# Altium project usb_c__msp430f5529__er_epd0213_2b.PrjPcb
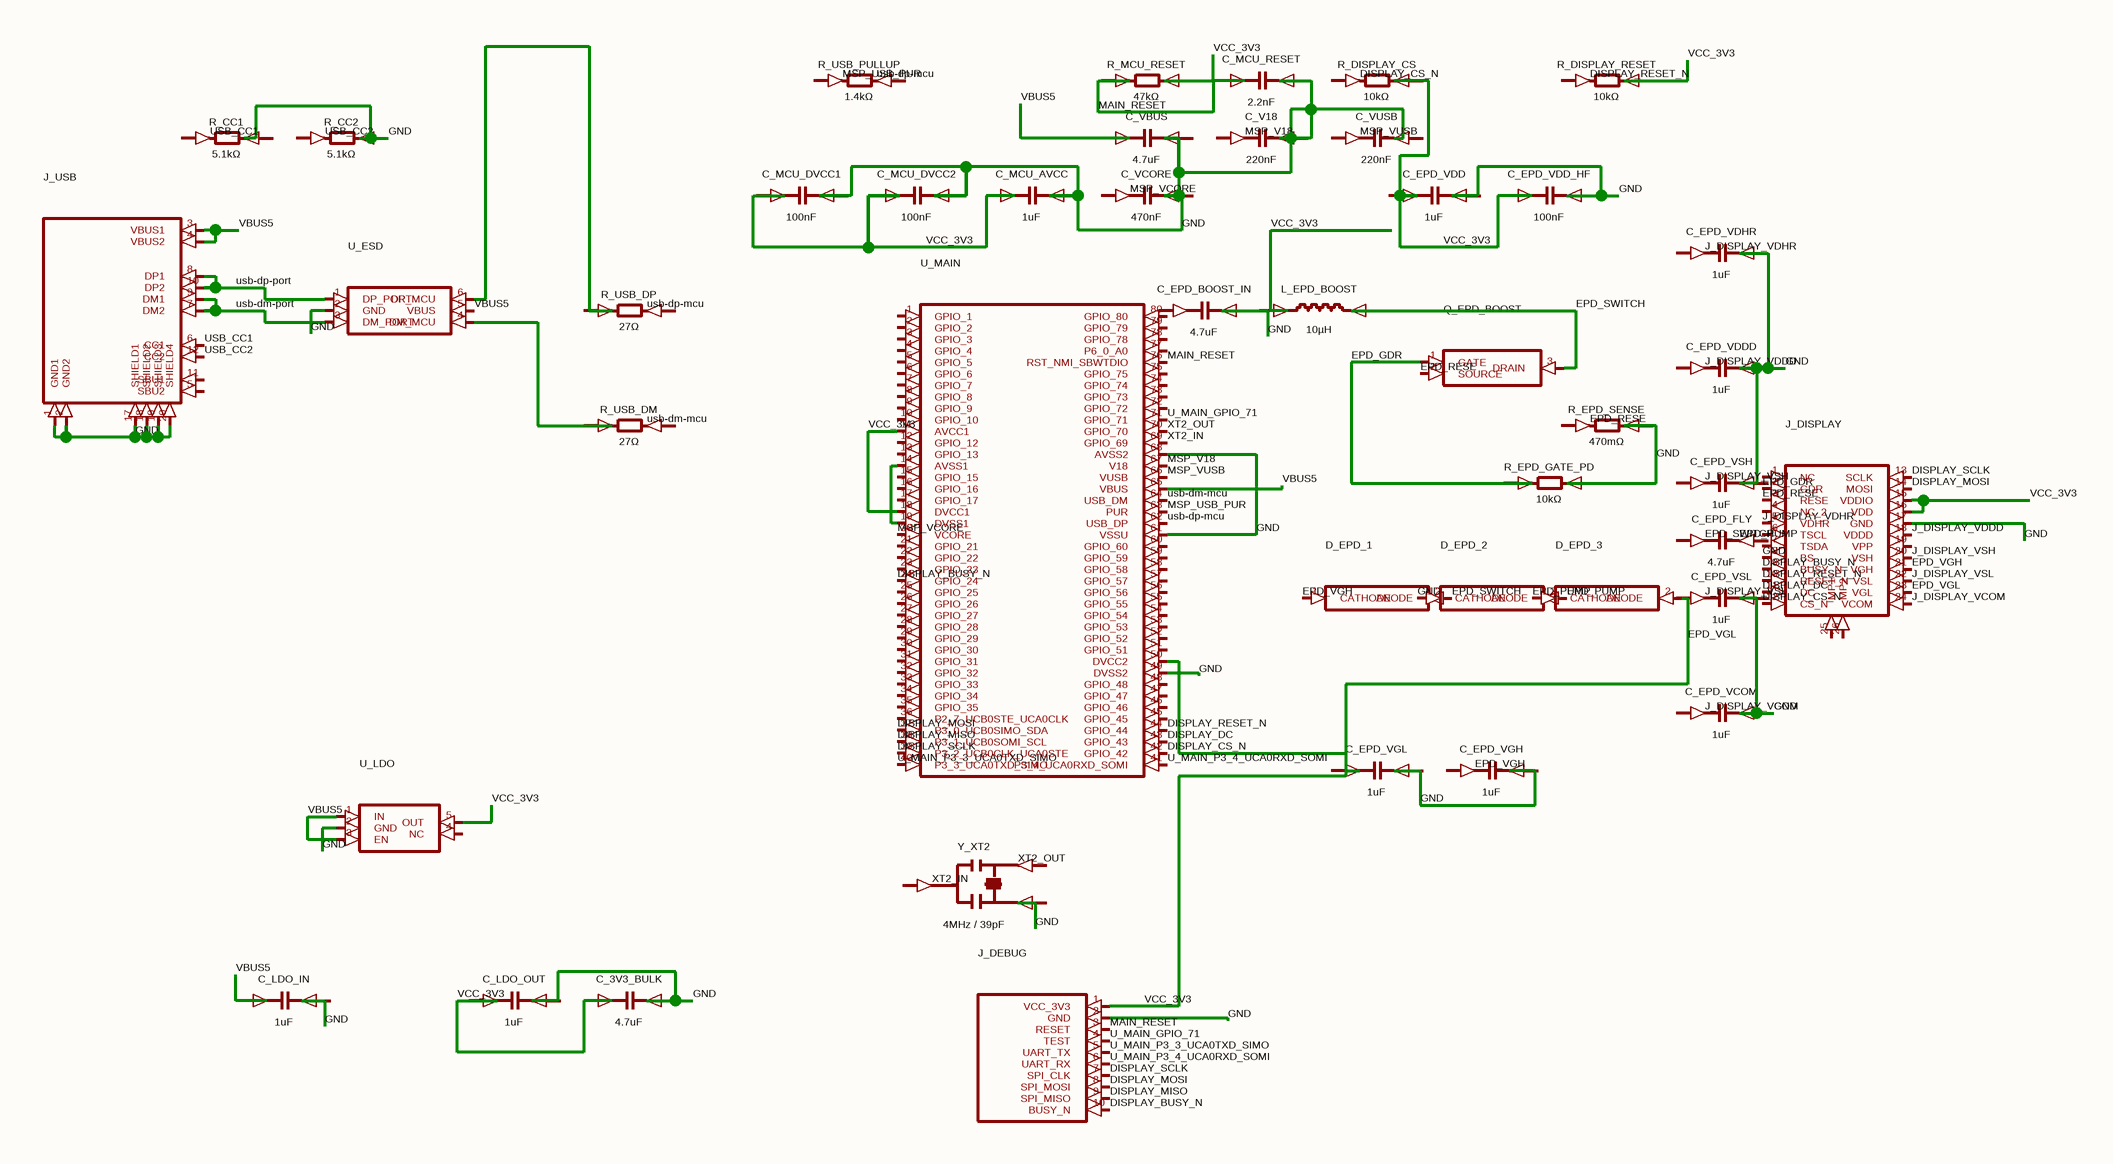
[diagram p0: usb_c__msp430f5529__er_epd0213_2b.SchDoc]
1 sheet, 44 parts. Net scope: global (net labels, ports and power ports of the same name join across sheets).
Board file: usb_c__msp430f5529__er_epd0213_2b.PcbDoc

## Sheet usb_c__msp430f5529__er_epd0213_2b.SchDoc
size 225 x 144 mm

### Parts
C_3V3_BULK  4.7uF
C_EPD_BOOST_IN  4.7uF
C_EPD_FLY  4.7uF
C_EPD_VCOM  1uF
C_EPD_VDD  1uF
C_EPD_VDD_HF  100nF
C_EPD_VDDD  1uF
C_EPD_VDHR  1uF
C_EPD_VGH  1uF
C_EPD_VGL  1uF
C_EPD_VSH  1uF
C_EPD_VSL  1uF
C_LDO_IN  1uF
C_LDO_OUT  1uF
C_MCU_AVCC  1uF
C_MCU_DVCC1  100nF
C_MCU_DVCC2  100nF
C_MCU_RESET  2.2nF
C_V18  220nF
C_VBUS  4.7uF
C_VCORE  470nF
C_VUSB  220nF
D_EPD_1  (no value)
D_EPD_2  (no value)
D_EPD_3  (no value)
J_DEBUG  (no value)
J_DISPLAY  (no value)
J_USB  (no value)
L_EPD_BOOST  10µH
Q_EPD_BOOST  (no value)
R_CC1  5.1kΩ
R_CC2  5.1kΩ
R_DISPLAY_CS  10kΩ
R_DISPLAY_RESET  10kΩ
R_EPD_GATE_PD  10kΩ
R_EPD_SENSE  470mΩ
R_MCU_RESET  47kΩ
R_USB_DM  27Ω
R_USB_DP  27Ω
R_USB_PULLUP  1.4kΩ
U_ESD  (no value)
U_LDO  (no value)
U_MAIN  (no value)
Y_XT2  4MHz / 39pF

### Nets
DISPLAY_BUSY_N: J_DEBUG.10(BUSY_N) J_DISPLAY.9(BUSY_N) U_MAIN.24(GPIO_24)
DISPLAY_CS_N: J_DISPLAY.12(CS_N) U_MAIN.42(GPIO_42)
DISPLAY_DC: J_DISPLAY.11(DC) U_MAIN.43(GPIO_43)
DISPLAY_MISO: J_DEBUG.9(SPI_MISO) U_MAIN.38(P3_1_UCB0SOMI_SCL)
DISPLAY_MOSI: J_DEBUG.8(SPI_MOSI) J_DISPLAY.14(MOSI) U_MAIN.37(P3_0_UCB0SIMO_SDA)
DISPLAY_RESET_N: J_DISPLAY.10(RESET_N) U_MAIN.44(GPIO_44)
DISPLAY_SCLK: J_DEBUG.7(SPI_CLK) J_DISPLAY.13(SCLK) U_MAIN.39(P3_2_UCB0CLK_UCA0STE)
EPD_GDR: J_DISPLAY.2(GDR) Q_EPD_BOOST.1(GATE) R_EPD_GATE_PD.1(anode)
EPD_PUMP: D_EPD_2.2(ANODE) D_EPD_3.1(CATHODE)
EPD_RESE: J_DISPLAY.3(RESE) Q_EPD_BOOST.2(SOURCE)
EPD_SWITCH: D_EPD_1.2(ANODE) L_EPD_BOOST.2(cathode) Q_EPD_BOOST.3(DRAIN)
EPD_VGH: D_EPD_1.1(CATHODE) J_DISPLAY.21(VGH)
EPD_VGL: C_3V3_BULK.1(pos) C_EPD_VDD_HF.1(pos) C_LDO_OUT.1(pos) C_MCU_AVCC.1(pos) C_MCU_DVCC1.1(pos) C_MCU_DVCC2.1(pos) C_MCU_RESET.1(pos) D_EPD_3.2(ANODE) J_DEBUG.1(VCC_3V3) J_DEBUG.3(RESET) J_DISPLAY.15(VDDIO) J_DISPLAY.16(VDD) J_DISPLAY.23(VGL) R_DISPLAY_CS.2(cathode) R_DISPLAY_RESET.2(cathode) R_MCU_RESET.1(anode) R_MCU_RESET.2(cathode) U_LDO.5(OUT) U_MAIN.11(AVCC1) U_MAIN.18(DVCC1) U_MAIN.50(DVCC2) U_MAIN.76(RST_NMI_SBWTDIO)  [also labelled MAIN_RESET, VCC_3V3]
GND: C_3V3_BULK.2(neg) C_EPD_BOOST_IN.2(neg) C_EPD_VCOM.2(neg) C_EPD_VDD_HF.2(neg) C_EPD_VDDD.2(neg) C_EPD_VDHR.2(neg) C_MCU_AVCC.2(neg) C_MCU_DVCC1.2(neg) C_MCU_DVCC2.2(neg) C_MCU_RESET.2(neg) C_V18.2(neg) D_EPD_2.1(CATHODE) J_DEBUG.2(GND) J_DISPLAY.8(BS) J_DISPLAY.17(GND) J_USB.1(GND1) J_USB.2(GND2) J_USB.17(SHIELD1) J_USB.18(SHIELD2) J_USB.19(SHIELD3) J_USB.20(SHIELD4) L_EPD_BOOST.1(anode) R_CC2.2(cathode) R_EPD_GATE_PD.2(cathode) R_EPD_SENSE.2(cathode) U_ESD.2(GND) U_LDO.2(GND) U_MAIN.49(DVSS2) U_MAIN.61(VSSU) U_MAIN.68(AVSS2)
J_DISPLAY_VCOM: J_DISPLAY.24(VCOM)
J_DISPLAY_VDDD: J_DISPLAY.18(VDDD)
J_DISPLAY_VDHR: J_DISPLAY.5(VDHR)
J_DISPLAY_VSH: J_DISPLAY.20(VSH)
J_DISPLAY_VSL: J_DISPLAY.22(VSL)
MSP_USB_PUR: U_MAIN.63(PUR)
MSP_V18: U_MAIN.67(V18)
MSP_VCORE: U_MAIN.20(VCORE)
MSP_VUSB: U_MAIN.66(VUSB)
U_MAIN_GPIO_71: J_DEBUG.4(TEST) U_MAIN.71(GPIO_71)
U_MAIN_P3_3_UCA0TXD_SIMO: J_DEBUG.5(UART_TX) U_MAIN.40(P3_3_UCA0TXD_SIMO)
U_MAIN_P3_4_UCA0RXD_SOMI: J_DEBUG.6(UART_RX) U_MAIN.41(P3_4_UCA0RXD_SOMI)
usb-dm-mcu: U_MAIN.64(USB_DM)
usb-dm-port: J_USB.7(DM2) J_USB.9(DM1) U_ESD.3(DM_PORT)
usb-dp-mcu: U_MAIN.62(USB_DP)
usb-dp-port: J_USB.8(DP1) J_USB.10(DP2) U_ESD.1(DP_PORT)
USB_CC1: J_USB.6(CC1)
USB_CC2: J_USB.12(CC2)
VBUS5: C_LDO_IN.1(pos) C_VBUS.1(pos) J_USB.3(VBUS1) J_USB.4(VBUS2) U_ESD.5(VBUS) U_LDO.1(IN) U_LDO.3(EN) U_MAIN.65(VBUS)
XT2_IN: U_MAIN.69(GPIO_69)
XT2_OUT: U_MAIN.70(GPIO_70)
NetR_USB_DM_1: R_USB_DM.1(anode) U_ESD.4(DM_MCU)
NetU_MAIN_14: U_MAIN.14(AVSS1) U_MAIN.19(DVSS1)

Not connected (* = marked no-connect by the designer): C_EPD_BOOST_IN 1(pos); C_EPD_FLY 1(pos) 2(neg); C_EPD_VCOM 1(pos); C_EPD_VDD 1(pos) 2(neg); C_EPD_VDDD 1(pos); C_EPD_VDHR 1(pos); C_EPD_VGH 1(pos) 2(neg); C_EPD_VGL 1(pos) 2(neg); C_EPD_VSH 1(pos) 2(neg); C_EPD_VSL 1(pos) 2(neg); C_LDO_IN 2(neg); C_LDO_OUT 2(neg); C_V18 1(pos); C_VBUS 2(neg); C_VCORE 1(pos) 2(neg); C_VUSB 1(pos) 2(neg); J_DISPLAY 1(NC) 4(NC_2) 6(TSCL) 7(TSDA) 19(VPP) 25(MP1) 26(MP2); J_USB 5(SBU2) 11(SBU1); R_CC1 1(anode) 2(cathode); R_CC2 1(anode); R_DISPLAY_CS 1(anode); R_DISPLAY_RESET 1(anode); R_EPD_SENSE 1(anode); R_USB_DM 2(cathode); R_USB_DP 1(anode) 2(cathode); R_USB_PULLUP 1(anode) 2(cathode); U_ESD 6(DP_MCU); U_LDO 4(NC); U_MAIN 1(GPIO_1) 2(GPIO_2) 3(GPIO_3) 4(GPIO_4) 5(GPIO_5) 6(GPIO_6) 7(GPIO_7) 8(GPIO_8) 9(GPIO_9) 10(GPIO_10) 12(GPIO_12) 13(GPIO_13) 15(GPIO_15) 16(GPIO_16) 17(GPIO_17) 21(GPIO_21) 22(GPIO_22) 23(GPIO_23) 25(GPIO_25) 26(GPIO_26) 27(GPIO_27) 28(GPIO_28) 29(GPIO_29) 30(GPIO_30) 31(GPIO_31) 32(GPIO_32) 33(GPIO_33) 34(GPIO_34) 35(GPIO_35) 36(P2_7_UCB0STE_UCA0CLK) 45(GPIO_45) 46(GPIO_46) 47(GPIO_47) 48(GPIO_48) 51(GPIO_51) 52(GPIO_52) 53(GPIO_53) 54(GPIO_54) 55(GPIO_55) 56(GPIO_56) 57(GPIO_57) 58(GPIO_58) 59(GPIO_59) 60(GPIO_60) 72(GPIO_72) 73(GPIO_73) 74(GPIO_74) 75(GPIO_75) 77(P6_0_A0) 78(GPIO_78) 79(GPIO_79) 80(GPIO_80); Y_XT2 1(pin1) 2(pin2) 3(pin3)

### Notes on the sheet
- Labels drawn without touching a wire or pin: DISPLAY_CS_N, DISPLAY_RESET_N, EPD_PUMP, EPD_RESE, EPD_SWITCH, EPD_VGH, J_DISPLAY_VCOM, J_DISPLAY_VDDD, J_DISPLAY_VDHR, J_DISPLAY_VSH, J_DISPLAY_VSL, MSP_USB_PUR, MSP_V18, MSP_VCORE, MSP_VUSB, usb-dm-mcu, usb-dp-mcu, USB_CC1, USB_CC2, XT2_IN, XT2_OUT

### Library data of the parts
C_3V3_BULK C_EPD_BOOST_IN C_EPD_FLY C_EPD_VCOM C_EPD_VDD C_EPD_VDD_HF C_EPD_VDDD C_EPD_VDHR C_EPD_VGH C_EPD_VGL C_EPD_VSH C_EPD_VSL C_LDO_IN C_LDO_OUT C_MCU_AVCC C_MCU_DVCC1 C_MCU_DVCC2 C_MCU_RESET C_V18 C_VBUS C_VCORE C_VUSB = capacitor_right
D_EPD_1 = D_EPD_1
D_EPD_2 = D_EPD_2
D_EPD_3 = D_EPD_3
J_DEBUG = J_DEBUG
J_DISPLAY = J_DISPLAY
J_USB = J_USB
L_EPD_BOOST = inductor_right
Q_EPD_BOOST = Q_EPD_BOOST
R_CC1 R_CC2 R_DISPLAY_CS R_DISPLAY_RESET R_EPD_GATE_PD R_EPD_SENSE R_MCU_RESET R_USB_DM R_USB_DP R_USB_PULLUP = boxresistor_right
U_ESD = U_ESD
U_LDO = U_LDO
U_MAIN = U_MAIN
Y_XT2 = resonator_right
